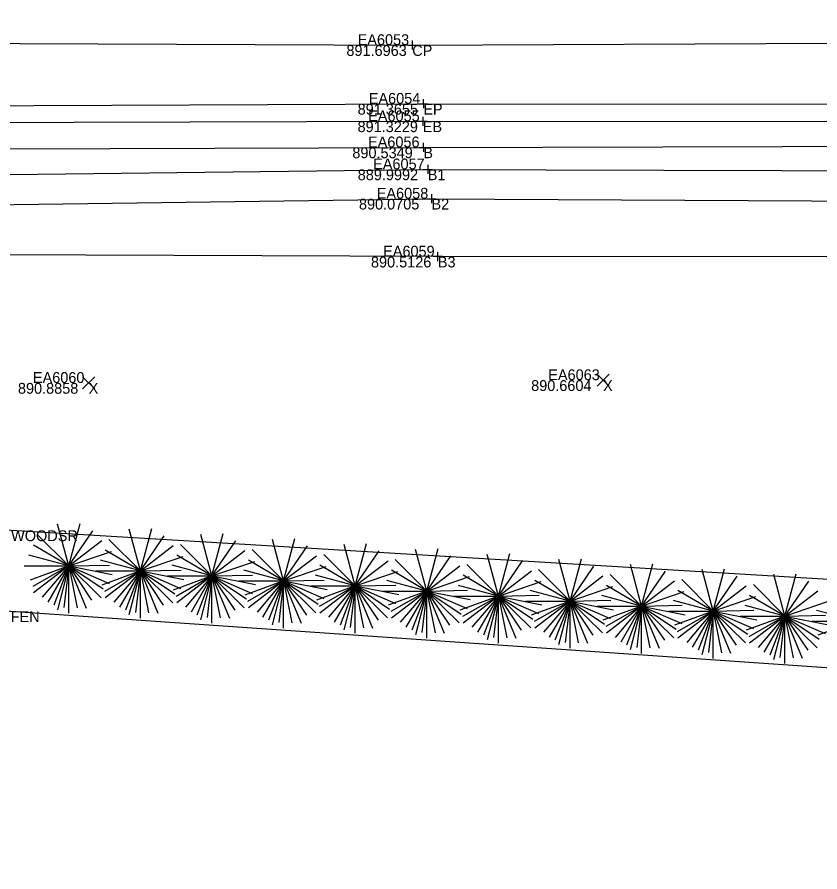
# Model space of a CAD drawing. Extents: x 179044 to 189691, y 286531 to 301257.
# Drawn here: x 179941.9 to 180030.9, y 300496.5 to 300591.3 of the extents above; entities that cross this region are included whole.
import ezdxf

# ---------------------------------------------------------------- set-up
doc = ezdxf.new("R2010")
doc.units = 0
for name, color, linetype in [('PV_X_COP', 7, 'Continuous'), ('PV_X_EOP', 7, 'Continuous'), ('PV_X_Shoulder_Aggregate', 7, 'Continuous'), ('RD_X_Fence', 7, 'Continuous'), ('SV_X_Break_Lines', 7, 'Continuous'), ('SV_X_Random_Point', 7, 'Continuous'), ('SV_X_Shot_Marker', 7, 'Continuous'), ('SV_X_Text_Comment', 7, 'Continuous'), ('SV_X_Text_Elevation', 7, 'Continuous'), ('SV_X_Text_Name', 7, 'Continuous'), ('VG_X_Cells', 7, 'Continuous'), ('VG_X_Text', 7, 'Continuous'), ('VG_X_Tree_Line_Lt', 7, 'Continuous')]:
    doc.layers.add(name, color=color, linetype=linetype)

msp = doc.modelspace()

# ---------------------------------------------------------------- linework, layer by layer
at = {"layer": 'PV_X_COP'}
msp.add_lwpolyline([(179370.611, 300584.893), (179476.831, 300585.936), (179562.951, 300586.92), (179659.852, 300587.603), (179771.173, 300587.773), (179881.154, 300588.595), (179985.728, 300588.166), (180079.826, 300588.612), (180147.691, 300589.874), (180172.034, 300590.636), (180187.456, 300591.905), (180203.618, 300593.325)], dxfattribs=at)
at = {"layer": 'PV_X_EOP'}
msp.add_lwpolyline([(179371.146, 300578.051), (179477.168, 300579.528), (179563.012, 300579.455), (179660.626, 300579.907), (179772.349, 300580.843), (179883.302, 300581.216), (179986.953, 300581.659), (180080.461, 300581.624), (180131.142, 300581.875), (180152.421, 300580.897), (180177.372, 300581.245), (180192.481, 300580.813), (180205.116, 300578.916), (180211.895, 300576.366), (180217.061, 300570.924), (180226.256, 300546.032), (180252.64, 300475.662), (180284.891, 300388.784), (180312.046, 300315.753), (180341.998, 300235.308)], dxfattribs=at)
at = {"layer": 'PV_X_Shoulder_Aggregate'}
msp.add_lwpolyline([(179563.451, 300578.229), (179660.977, 300578.016), (179772.748, 300578.901), (179883.7, 300579.446), (179986.895, 300579.719), (180080.262, 300579.655), (180131.517, 300579.632), (180152.892, 300578.404), (180177.169, 300578.87), (180192.854, 300577.824), (180203.732, 300575.396), (180212.869, 300569.272), (180224.05, 300544.426), (180250.422, 300474.503), (180282.665, 300386.992), (180309.922, 300313.986), (180339.844, 300234.334)], dxfattribs=at)
at = {"layer": 'RD_X_Fence'}
msp.add_lwpolyline([(179565.425, 300550.823), (179667.832, 300544.252), (179812.225, 300533.926), (179896.206, 300528.356), (179941.193, 300525.399), (180078.773, 300515.902), (180168.337, 300509.719), (180196.88, 300447.723), (180266.667, 300296.146), (180285.875, 300252.935)], dxfattribs=at)
at = {"layer": 'SV_X_Break_Lines'}
for points in [[(179565.115, 300573.15), (179662.025, 300574.398), (179773.068, 300575.457), (179882.867, 300576.482), (179986.954, 300576.827), (180079.906, 300577.073), (180132.276, 300575.162), (180173.558, 300573.472), (180187.352, 300573.774), (180198.853, 300570.766)], [(179565.766, 300571.109), (179663.199, 300570.888), (179773.087, 300572.831), (179882.326, 300573.106), (179987.447, 300574.391), (180079.006, 300574.101), (180132.144, 300569.99), (180164.614, 300565.351), (180185.409, 300564.026)], [(179565.763, 300567.872), (179663.335, 300568.017), (179772.883, 300569.466), (179881.609, 300569.697), (179987.857, 300571.139), (180079.155, 300570.638), (180132.418, 300565.887), (180165.824, 300561.088), (180185.221, 300560.101)], [(180320.902, 300212.184), (180282.069, 300307.438), (180254.033, 300376.286), (180214.216, 300457.225), (180192.833, 300518.475), (180187.002, 300524.649), (180178.544, 300551.918), (180167.492, 300556.189), (180133.433, 300560.27), (180078.668, 300564.705), (179988.563, 300564.714), (179881.16, 300565.14), (179774.574, 300564.41), (179665.201, 300563.792), (179565.532, 300563.693)]]:
    msp.add_lwpolyline(points, dxfattribs=at)
at = {"layer": 'SV_X_Random_Point'}
for p, q in [((179949.173, 300550.045), (179950.506, 300551.38)), ((179949.173, 300551.38), (179950.506, 300550.045)), ((180006.22, 300550.35), (180007.553, 300551.685)), ((180006.22, 300551.685), (180007.553, 300550.35))]:
    msp.add_line(p, q, dxfattribs=at)
at = {"layer": 'SV_X_Shot_Marker'}
for p, q in [((179985.228, 300588.168), (179986.228, 300588.164)), ((179985.73, 300588.666), (179985.726, 300587.666)), ((179985.728, 300588.166), (179985.728, 300588.166)), ((179986.453, 300581.657), (179987.453, 300581.662)), ((179986.951, 300582.159), (179986.955, 300581.159)), ((179986.953, 300581.659), (179986.953, 300581.659)), ((179986.395, 300579.718), (179987.395, 300579.721)), ((179986.894, 300580.219), (179986.897, 300579.219)), ((179986.895, 300579.719), (179986.895, 300579.719)), ((179986.454, 300576.825), (179987.454, 300576.828)), ((179986.952, 300577.327), (179986.956, 300576.327)), ((179986.954, 300576.827), (179986.954, 300576.827)), ((179987.44, 300574.891), (179987.453, 300573.891)), ((179986.947, 300574.385), (179987.947, 300574.397)), ((179987.447, 300574.391), (179987.447, 300574.391)), ((179987.357, 300571.133), (179988.357, 300571.146)), ((179987.85, 300571.639), (179987.864, 300570.639)), ((179987.857, 300571.139), (179987.857, 300571.139)), ((179988.563, 300564.214), (179988.563, 300565.214)), ((179989.063, 300564.714), (179988.063, 300564.714)), ((179988.563, 300564.714), (179988.563, 300564.714))]:
    msp.add_line(p, q, dxfattribs=at)
at = {"layer": 'VG_X_Cells'}
for p, q in [((179947.632, 300530.424), (179946.397, 300535.037)), ((179947.632, 300530.424), (179948.889, 300535.122)), ((179947.632, 300530.424), (179944.142, 300533.91)), ((179947.632, 300530.424), (179950.287, 300534.309)), ((179955.571, 300529.867), (179954.336, 300534.481)), ((179955.571, 300529.867), (179956.828, 300534.566)), ((179963.513, 300529.311), (179962.278, 300533.924)), ((179963.513, 300529.311), (179964.769, 300534.009)), ((179947.632, 300530.424), (179951.289, 300533.229)), ((179955.571, 300529.867), (179952.081, 300533.354)), ((179955.571, 300529.867), (179958.226, 300533.752)), ((179963.513, 300529.311), (179966.168, 300533.196)), ((179971.454, 300528.754), (179970.219, 300533.368)), ((179971.454, 300528.754), (179972.711, 300533.453)), ((179979.396, 300528.198), (179980.653, 300532.896)), ((179947.632, 300530.424), (179943.726, 300532.72)), ((179947.632, 300530.424), (179952.369, 300532.03)), ((179955.571, 300529.867), (179951.665, 300532.164)), ((179955.571, 300529.867), (179959.228, 300532.672)), ((179963.513, 300529.311), (179960.023, 300532.798)), ((179963.513, 300529.311), (179967.169, 300532.116)), ((179971.454, 300528.754), (179967.964, 300532.241)), ((179971.454, 300528.754), (179974.109, 300532.639)), ((179979.396, 300528.198), (179978.161, 300532.811)), ((179979.396, 300528.198), (179982.051, 300532.083)), ((179987.337, 300527.642), (179986.102, 300532.255)), ((179987.337, 300527.642), (179988.594, 300532.34)), ((179947.632, 300530.424), (179943.219, 300531.607)), ((179955.571, 300529.867), (179951.158, 300531.051)), ((179955.571, 300529.867), (179960.308, 300531.474)), ((179963.513, 300529.311), (179959.606, 300531.608)), ((179971.454, 300528.754), (179967.548, 300531.051)), ((179971.454, 300528.754), (179975.111, 300531.559)), ((179979.396, 300528.198), (179975.906, 300531.685)), ((179979.396, 300528.198), (179983.053, 300531.003)), ((179987.337, 300527.642), (179983.847, 300531.128)), ((179987.337, 300527.642), (179989.992, 300531.527)), ((179995.279, 300527.085), (179994.044, 300531.698)), ((179995.279, 300527.085), (179996.536, 300531.783)), ((180003.221, 300526.529), (180001.986, 300531.142)), ((180003.221, 300526.529), (180004.477, 300531.227)), ((179942.697, 300530.424), (179947.632, 300530.424)), ((179947.632, 300530.424), (179943.342, 300528.862)), ((179947.632, 300530.424), (179943.649, 300528.142)), ((179947.632, 300530.424), (179943.726, 300527.429)), ((179947.632, 300530.424), (179944.687, 300526.957)), ((179947.632, 300530.424), (179945.314, 300526.409)), ((179947.632, 300530.424), (179945.967, 300526.084)), ((179947.632, 300530.424), (179946.369, 300525.567)), ((179947.632, 300530.424), (179947.091, 300525.832)), ((179947.632, 300530.424), (179952.142, 300530.515)), ((179947.632, 300525.184), (179947.632, 300530.424)), ((179947.632, 300530.424), (179948.554, 300525.787)), ((179947.632, 300530.424), (179949.566, 300525.755)), ((179947.632, 300530.424), (179950.169, 300526.63)), ((179947.632, 300530.424), (179951.221, 300526.902)), ((179947.632, 300530.424), (179951.454, 300527.869)), ((179947.632, 300530.424), (179952.097, 300528.482)), ((179947.632, 300530.424), (179952.461, 300529.465)), ((179963.513, 300529.311), (179959.099, 300530.494)), ((179963.513, 300529.311), (179968.249, 300530.918)), ((179971.454, 300528.754), (179976.191, 300530.361)), ((179979.396, 300528.198), (179975.489, 300530.495)), ((179987.337, 300527.642), (179990.994, 300530.447)), ((179995.279, 300527.085), (179991.789, 300530.572)), ((179995.279, 300527.085), (179997.934, 300530.97)), ((180003.221, 300526.529), (180005.876, 300530.414)), ((180011.162, 300525.972), (180009.927, 300530.585)), ((180011.162, 300525.972), (180012.419, 300530.67)), ((180019.104, 300525.416), (180020.36, 300530.114)), ((179950.636, 300529.867), (179955.571, 300529.867)), ((179955.571, 300529.867), (179951.281, 300528.306)), ((179955.571, 300529.867), (179951.588, 300527.586)), ((179955.571, 300529.867), (179951.665, 300526.872)), ((179955.571, 300529.867), (179952.626, 300526.401)), ((179955.571, 300529.867), (179953.253, 300525.852)), ((179955.571, 300529.867), (179953.906, 300525.527)), ((179955.571, 300529.867), (179954.308, 300525.011)), ((179955.571, 300529.867), (179955.03, 300525.276)), ((179955.571, 300529.867), (179960.081, 300529.959)), ((179955.571, 300524.627), (179955.571, 300529.867)), ((179955.571, 300529.867), (179956.493, 300525.231)), ((179955.571, 300529.867), (179957.505, 300525.199)), ((179955.571, 300529.867), (179958.108, 300526.074)), ((179955.571, 300529.867), (179959.16, 300526.346)), ((179955.571, 300529.867), (179959.393, 300527.312)), ((179955.571, 300529.867), (179960.036, 300527.926)), ((179955.571, 300529.867), (179960.4, 300528.909)), ((179958.578, 300529.311), (179963.513, 300529.311)), ((179963.513, 300529.311), (179959.223, 300527.749)), ((179963.513, 300529.311), (179959.529, 300527.029)), ((179963.513, 300529.311), (179959.606, 300526.316)), ((179963.513, 300529.311), (179960.568, 300525.844)), ((179963.513, 300529.311), (179961.194, 300525.296)), ((179963.513, 300529.311), (179961.848, 300524.971)), ((179963.513, 300529.311), (179962.249, 300524.454)), ((179963.513, 300529.311), (179962.971, 300524.719)), ((179963.513, 300529.311), (179968.023, 300529.403)), ((179963.513, 300524.071), (179963.513, 300529.311)), ((179963.513, 300529.311), (179964.434, 300524.674)), ((179963.513, 300529.311), (179965.446, 300524.643)), ((179963.513, 300529.311), (179966.049, 300525.518)), ((179963.513, 300529.311), (179967.101, 300525.789)), ((179963.513, 300529.311), (179967.334, 300526.756)), ((179963.513, 300529.311), (179967.978, 300527.369)), ((179963.513, 300529.311), (179968.341, 300528.353)), ((179971.454, 300528.754), (179967.041, 300529.938)), ((179979.396, 300528.198), (179974.983, 300529.381)), ((179979.396, 300528.198), (179984.133, 300529.805)), ((179987.337, 300527.642), (179983.431, 300529.938)), ((179987.337, 300527.642), (179992.074, 300529.248)), ((179995.279, 300527.085), (179991.372, 300529.382)), ((179995.279, 300527.085), (179998.936, 300529.89)), ((180003.221, 300526.529), (179999.731, 300530.015)), ((180003.221, 300526.529), (180006.877, 300529.334)), ((180011.162, 300525.972), (180007.672, 300529.459)), ((180011.162, 300525.972), (180013.817, 300529.857)), ((180019.104, 300525.416), (180017.869, 300530.029)), ((180019.104, 300525.416), (180021.759, 300529.301)), ((180027.045, 300524.859), (180025.81, 300529.473)), ((180027.045, 300524.859), (180028.302, 300529.558)), ((179966.519, 300528.754), (179971.454, 300528.754)), ((179971.454, 300528.754), (179967.164, 300527.193)), ((179971.454, 300528.754), (179967.471, 300526.473)), ((179971.454, 300528.754), (179967.548, 300525.759)), ((179971.454, 300528.754), (179968.509, 300525.288)), ((179971.454, 300528.754), (179969.136, 300524.739)), ((179971.454, 300528.754), (179969.789, 300524.414)), ((179971.454, 300528.754), (179970.191, 300523.898)), ((179971.454, 300528.754), (179970.913, 300524.163)), ((179971.454, 300528.754), (179975.964, 300528.846)), ((179971.454, 300523.514), (179971.454, 300528.754)), ((179971.454, 300528.754), (179972.376, 300524.118)), ((179971.454, 300528.754), (179973.388, 300524.086)), ((179971.454, 300528.754), (179973.991, 300524.961)), ((179971.454, 300528.754), (179975.043, 300525.233)), ((179971.454, 300528.754), (179975.276, 300526.199)), ((179971.454, 300528.754), (179975.919, 300526.813)), ((179971.454, 300528.754), (179976.283, 300527.796)), ((179974.461, 300528.198), (179979.396, 300528.198)), ((179979.396, 300528.198), (179975.106, 300526.636)), ((179979.396, 300528.198), (179975.413, 300525.916)), ((179979.396, 300528.198), (179975.489, 300525.203)), ((179979.396, 300528.198), (179976.451, 300524.731)), ((179979.396, 300528.198), (179977.078, 300524.183)), ((179979.396, 300528.198), (179977.731, 300523.858)), ((179979.396, 300528.198), (179978.133, 300523.341)), ((179979.396, 300528.198), (179978.854, 300523.606)), ((179979.396, 300528.198), (179983.906, 300528.29)), ((179979.396, 300522.958), (179979.396, 300528.198)), ((179979.396, 300528.198), (179980.318, 300523.561)), ((179979.396, 300528.198), (179981.329, 300523.53)), ((179979.396, 300528.198), (179981.933, 300524.405)), ((179979.396, 300528.198), (179982.984, 300524.676)), ((179979.396, 300528.198), (179983.218, 300525.643)), ((179979.396, 300528.198), (179983.861, 300526.256)), ((179979.396, 300528.198), (179984.224, 300527.24)), ((179987.337, 300527.642), (179982.924, 300528.825)), ((179995.279, 300527.085), (179990.866, 300528.268)), ((179995.279, 300527.085), (180000.016, 300528.692)), ((180003.221, 300526.529), (179999.314, 300528.825)), ((180011.162, 300525.972), (180007.255, 300528.269)), ((180011.162, 300525.972), (180014.819, 300528.777)), ((180019.104, 300525.416), (180015.614, 300528.902)), ((180019.104, 300525.416), (180022.76, 300528.221)), ((180027.045, 300524.859), (180023.555, 300528.346)), ((180027.045, 300524.859), (180029.7, 300528.744)), ((179982.402, 300527.642), (179987.337, 300527.642)), ((179987.337, 300527.642), (179983.047, 300526.08)), ((179987.337, 300527.642), (179983.354, 300525.36)), ((179987.337, 300527.642), (179983.431, 300524.647)), ((179987.337, 300527.642), (179984.392, 300524.175)), ((179987.337, 300527.642), (179985.019, 300523.627)), ((179987.337, 300527.642), (179985.672, 300523.302)), ((179987.337, 300527.642), (179986.074, 300522.785)), ((179987.337, 300527.642), (179986.796, 300523.05)), ((179987.337, 300527.642), (179991.847, 300527.733)), ((179987.337, 300522.402), (179987.337, 300527.642)), ((179987.337, 300527.642), (179988.259, 300523.005)), ((179987.337, 300527.642), (179989.271, 300522.973)), ((179987.337, 300527.642), (179989.874, 300523.848)), ((179987.337, 300527.642), (179990.926, 300524.12)), ((179987.337, 300527.642), (179991.159, 300525.087)), ((179987.337, 300527.642), (179991.802, 300525.7)), ((179987.337, 300527.642), (179992.166, 300526.683)), ((180003.221, 300526.529), (179998.807, 300527.712)), ((180003.221, 300526.529), (180007.957, 300528.135)), ((180011.162, 300525.972), (180015.899, 300527.579)), ((180019.104, 300525.416), (180015.197, 300527.712)), ((180027.045, 300524.859), (180030.702, 300527.664)), ((179990.344, 300527.085), (179995.279, 300527.085)), ((179995.279, 300527.085), (179990.989, 300525.523)), ((179995.279, 300527.085), (179991.296, 300524.803)), ((179995.279, 300527.085), (179991.372, 300524.09)), ((179995.279, 300527.085), (179992.334, 300523.618)), ((179995.279, 300527.085), (179992.961, 300523.07)), ((179995.279, 300527.085), (179993.614, 300522.745)), ((179995.279, 300527.085), (179994.016, 300522.228)), ((179995.279, 300527.085), (179994.737, 300522.493)), ((179995.279, 300527.085), (179999.789, 300527.177)), ((179995.279, 300521.845), (179995.279, 300527.085)), ((179995.279, 300527.085), (179996.201, 300522.448)), ((179995.279, 300527.085), (179997.212, 300522.417)), ((179995.279, 300527.085), (179997.816, 300523.292)), ((179995.279, 300527.085), (179998.867, 300523.563)), ((179995.279, 300527.085), (179999.101, 300524.53)), ((179995.279, 300527.085), (179999.744, 300525.143)), ((179995.279, 300527.085), (180000.107, 300526.127)), ((179998.286, 300526.529), (180003.221, 300526.529)), ((180003.221, 300526.529), (179998.931, 300524.967)), ((180003.221, 300526.529), (179999.237, 300524.247)), ((180003.221, 300526.529), (179999.314, 300523.534)), ((180003.221, 300526.529), (180000.276, 300523.062)), ((180003.221, 300526.529), (180000.902, 300522.514)), ((180003.221, 300526.529), (180001.556, 300522.189)), ((180003.221, 300526.529), (180001.957, 300521.672)), ((180003.221, 300526.529), (180002.679, 300521.937)), ((180003.221, 300526.529), (180007.731, 300526.62)), ((180003.221, 300521.289), (180003.221, 300526.529)), ((180003.221, 300526.529), (180004.142, 300521.892)), ((180003.221, 300526.529), (180005.154, 300521.86)), ((180003.221, 300526.529), (180005.757, 300522.735)), ((180003.221, 300526.529), (180006.809, 300523.007)), ((180003.221, 300526.529), (180007.042, 300523.974)), ((180003.221, 300526.529), (180007.686, 300524.587)), ((180003.221, 300526.529), (180008.049, 300525.57)), ((180011.162, 300525.972), (180006.749, 300527.155)), ((180019.104, 300525.416), (180014.69, 300526.599)), ((180019.104, 300525.416), (180023.84, 300527.022)), ((180027.045, 300524.859), (180023.139, 300527.156)), ((180027.045, 300524.859), (180031.782, 300526.466)), ((180006.227, 300525.972), (180011.162, 300525.972)), ((180011.162, 300525.972), (180006.872, 300524.41)), ((180011.162, 300525.972), (180007.179, 300523.69)), ((180011.162, 300525.972), (180007.255, 300522.977)), ((180011.162, 300525.972), (180008.217, 300522.505)), ((180011.162, 300525.972), (180008.844, 300521.957)), ((180011.162, 300525.972), (180009.497, 300521.632)), ((180011.162, 300525.972), (180009.899, 300521.115)), ((180011.162, 300525.972), (180010.62, 300521.38)), ((180011.162, 300525.972), (180015.672, 300526.064)), ((180011.162, 300520.732), (180011.162, 300525.972)), ((180011.162, 300525.972), (180012.084, 300521.335)), ((180011.162, 300525.972), (180013.095, 300521.304)), ((180011.162, 300525.972), (180013.699, 300522.179)), ((180011.162, 300525.972), (180014.75, 300522.45)), ((180011.162, 300525.972), (180014.984, 300523.417)), ((180011.162, 300525.972), (180015.627, 300524.03)), ((180011.162, 300525.972), (180015.99, 300525.014)), ((180014.169, 300525.416), (180019.104, 300525.416)), ((180019.104, 300525.416), (180014.814, 300523.854)), ((180019.104, 300525.416), (180015.12, 300523.134)), ((180019.104, 300525.416), (180015.197, 300522.421)), ((180019.104, 300525.416), (180016.159, 300521.949)), ((180019.104, 300525.416), (180016.785, 300521.401)), ((180019.104, 300525.416), (180017.439, 300521.076)), ((180019.104, 300525.416), (180017.84, 300520.559)), ((180019.104, 300525.416), (180018.562, 300520.824)), ((180019.104, 300525.416), (180023.614, 300525.507)), ((180019.104, 300520.176), (180019.104, 300525.416)), ((180019.104, 300525.416), (180020.025, 300520.779)), ((180019.104, 300525.416), (180021.037, 300520.747)), ((180019.104, 300525.416), (180021.64, 300521.622)), ((180019.104, 300525.416), (180022.692, 300521.894)), ((180019.104, 300525.416), (180022.925, 300522.861)), ((180019.104, 300525.416), (180023.569, 300523.474)), ((180019.104, 300525.416), (180023.932, 300524.457)), ((180027.045, 300524.859), (180022.632, 300526.043)), ((180034.987, 300524.303), (180030.573, 300525.486)), ((180022.11, 300524.859), (180027.045, 300524.859)), ((180027.045, 300524.859), (180022.755, 300523.298)), ((180027.045, 300524.859), (180023.062, 300522.578)), ((180027.045, 300524.859), (180023.139, 300521.864)), ((180027.045, 300524.859), (180024.1, 300521.393)), ((180027.045, 300524.859), (180024.727, 300520.844)), ((180027.045, 300524.859), (180025.38, 300520.519)), ((180027.045, 300524.859), (180025.782, 300520.003)), ((180027.045, 300524.859), (180026.504, 300520.268)), ((180027.045, 300524.859), (180031.555, 300524.951)), ((180027.045, 300519.619), (180027.045, 300524.859)), ((180027.045, 300524.859), (180027.967, 300520.223)), ((180027.045, 300524.859), (180028.979, 300520.191)), ((180027.045, 300524.859), (180029.582, 300521.066)), ((180027.045, 300524.859), (180030.634, 300521.338)), ((180027.045, 300524.859), (180030.867, 300522.304)), ((180027.045, 300524.859), (180031.51, 300522.918)), ((180027.045, 300524.859), (180031.874, 300523.901)), ((180030.052, 300524.303), (180034.987, 300524.303)), ((180034.987, 300524.303), (180030.697, 300522.741))]:
    msp.add_line(p, q, dxfattribs=at)
at = {"layer": 'VG_X_Tree_Line_Lt'}
msp.add_lwpolyline([(179569.069, 300551.827), (179569.572, 300561.616), (179669.01, 300553.205), (179812.545, 300543.336), (179895.927, 300538.89), (179941.238, 300534.37), (180108.398, 300524.388), (180109.229, 300515.004)], dxfattribs=at)

# ---------------------------------------------------------------- texts
at = {"layer": 'SV_X_Text_Comment'}
for s, height, p in [('CP', 1.2, (179985.728, 300586.966)), ('EP', 1.2, (179986.953, 300580.459)), ('EB', 1.2, (179986.895, 300578.519)), ('B', 1.2, (179986.954, 300575.627)), ('B1', 1.2, (179987.447, 300573.191)), ('B2', 1.2, (179987.857, 300569.939)), ('B3', 1.2, (179988.563, 300563.514)), ('X', 1.2, (180006.887, 300549.818)), ('X', 1.2, (179949.839, 300549.513)), ('WOODSR', 1.2, (179941.238, 300533.17)), ('TE', 0.12, (179947.632, 300530.304)), ('TE', 0.12, (179955.571, 300529.747)), ('TE', 0.12, (179963.513, 300529.191)), ('TE', 0.12, (179971.454, 300528.634)), ('TE', 0.12, (179979.396, 300528.078)), ('TE', 0.12, (179987.337, 300527.522)), ('TE', 0.12, (179995.279, 300526.965)), ('TE', 0.12, (180003.221, 300526.409)), ('FEN', 1.2, (179941.193, 300524.199)), ('TE', 0.12, (180011.162, 300525.852)), ('TE', 0.12, (180019.104, 300525.296)), ('TE', 0.12, (180027.045, 300524.739))]:
    msp.add_text(s, height=height, dxfattribs=at).set_placement(p)
at = {"layer": 'SV_X_Text_Elevation'}
for s, p in [('891.6963', (179978.425, 300586.966)), ('891.3655', (179979.669, 300580.459)), ('891.3229', (179979.659, 300578.519)), ('890.5349', (179979.084, 300575.627)), ('889.9992', (179979.68, 300573.191)), ('890.0705', (179979.817, 300569.939)), ('890.5126', (179981.147, 300563.514)), ('890.6604', (179998.912, 300549.818)), ('890.8858', (179941.997, 300549.513))]:
    msp.add_text(s, height=1.2, dxfattribs=at).set_placement(p)
at = {"layer": 'SV_X_Text_Name'}
for s, p in [('EA6053', (179979.672, 300588.166)), ('EA6054', (179980.906, 300581.659)), ('EA6055', (179980.839, 300579.719)), ('EA6056', (179980.822, 300576.827)), ('EA6057', (179981.39, 300574.391)), ('EA6058', (179981.791, 300571.139)), ('EA6059', (179982.497, 300564.714)), ('EA6060', (179943.66, 300550.713)), ('EA6063', (180000.812, 300551.018))]:
    msp.add_text(s, height=1.2, dxfattribs=at).set_placement(p)
at = {"layer": 'VG_X_Text'}
for p in [(179947.632, 300530.424), (179955.571, 300529.867), (179963.513, 300529.311), (179971.454, 300528.754), (179979.396, 300528.198), (179987.337, 300527.642), (179995.279, 300527.085), (180003.221, 300526.529), (180011.162, 300525.972), (180019.104, 300525.416), (180027.045, 300524.859)]:
    msp.add_text(' NOTE:8', height=0.12, dxfattribs=at).set_placement(p)

doc.saveas('drawing.dxf')
